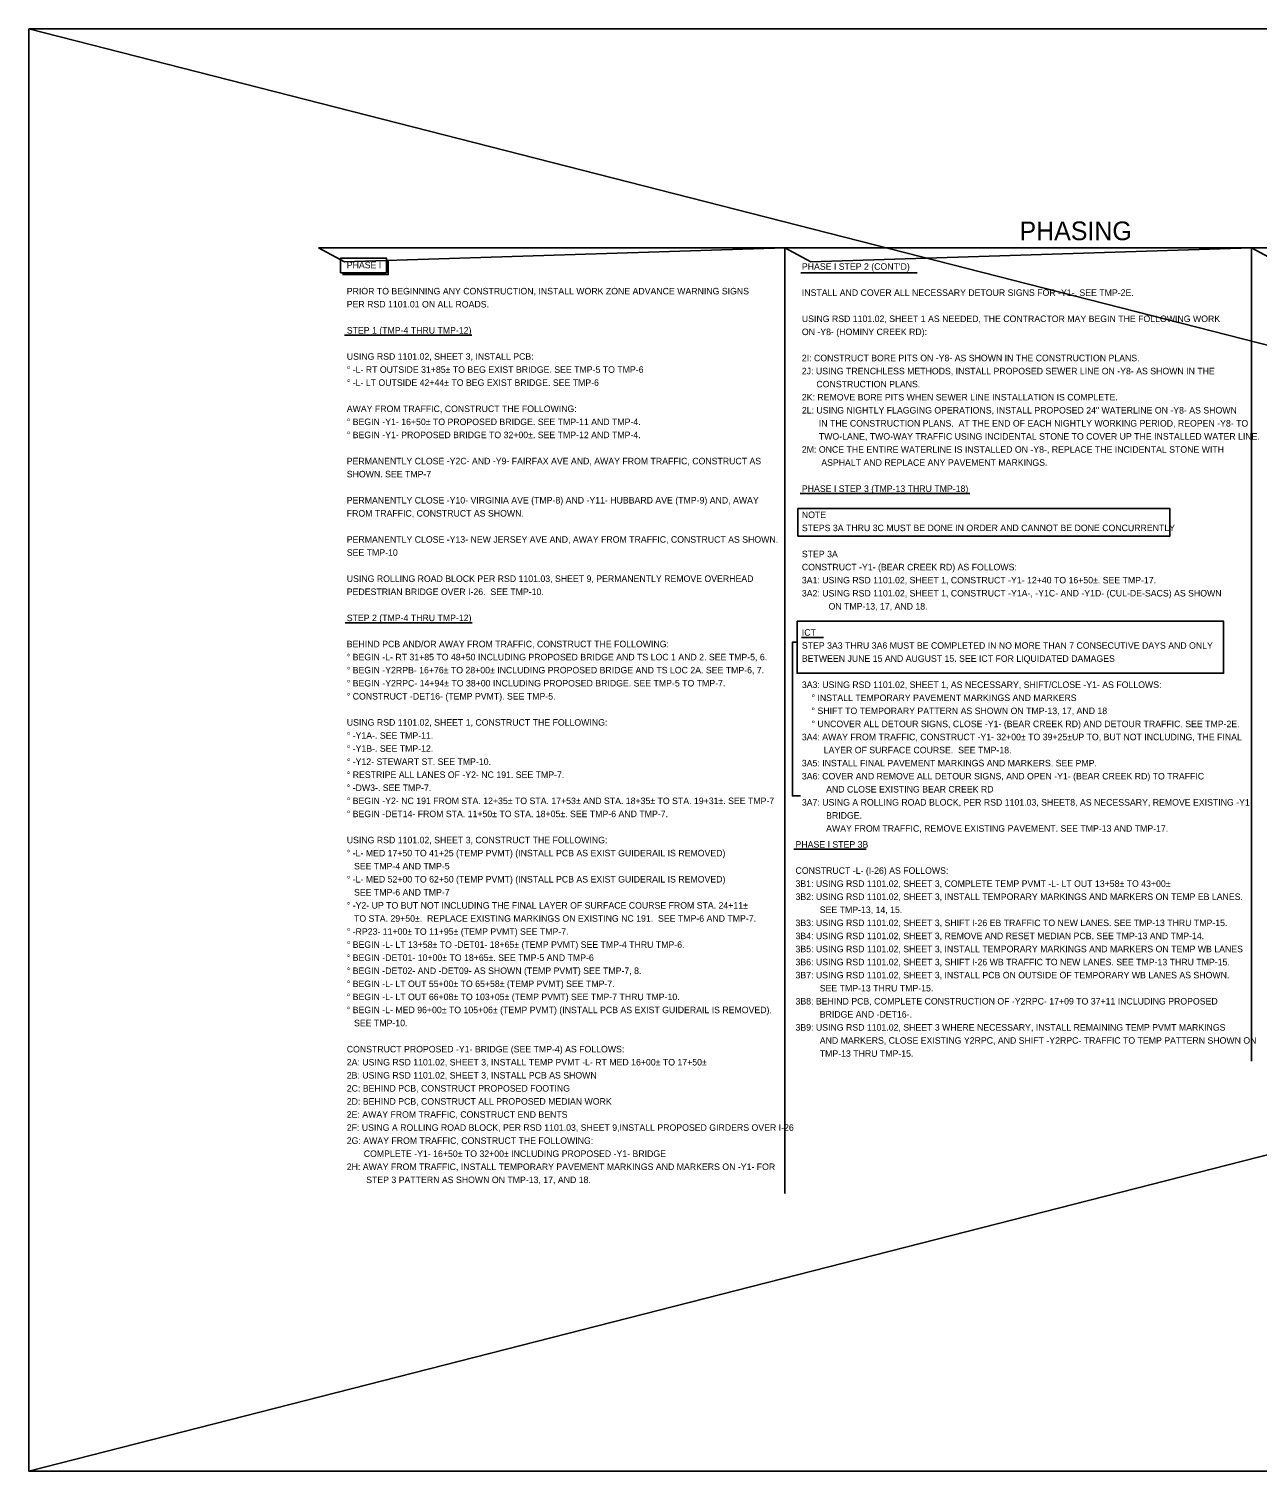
# Model space of a CAD drawing. Extents: x 2483905 to 2494512, y 366160 to 372330.
# Drawn here: x 2486701 to 2488018, y 368441 to 369986 of the extents above; entities that cross this region are included whole.
import ezdxf

# ---------------------------------------------------------------- set-up
doc = ezdxf.new("R2010")
doc.units = 0
for name, color, linetype in [('Scratch_Level_4', 7, 'Continuous'), ('Scratch_Level_6', 7, 'Continuous'), ('TC SHEET BORDER LINE THIN', 7, 'Continuous'), ('TC SHEET TEXT', 7, 'Continuous')]:
    doc.layers.add(name, color=color, linetype=linetype)

msp = doc.modelspace()

# ---------------------------------------------------------------- linework, layer by layer
at = {"layer": 'Scratch_Level_4'}
for p, q in [((2486701.2, 368441.1), (2492754.6, 369986.2)), ((2486701.2, 369986.2), (2492754.6, 368441.1))]:
    msp.add_line(p, q, dxfattribs=at)
msp.add_lwpolyline([(2486701.2, 369986.2), (2492754.6, 369986.2), (2492754.6, 368441.1), (2486701.2, 368441.1)], close=True, dxfattribs=at)
at = {"layer": 'Scratch_Level_6'}
msp.add_lwpolyline([(2487011.6, 369751.7), (2487039.5, 369736.7), (2487511.6, 369751.7), (2487539.5, 369736.7), (2488011.6, 369751.7), (2488039.5, 369736.7)], dxfattribs=at)
at = {"layer": 'TC SHEET BORDER LINE THIN'}
for p, q in [((2488511.6, 369751.7), (2487011.6, 369751.7)), ((2487511.6, 369751.7), (2487511.6, 368738.5)), ((2488011.6, 369751.6), (2488011.6, 368880.2)), ((2487528.7, 369725), (2487646.8, 369725)), ((2487535.4, 369725), (2487653.5, 369725)), ((2487039.7, 369658.1), (2487039.7, 369658.1)), ((2487039.7, 369658.1), (2487176, 369658.1)), ((2487528.1, 369488.5), (2487528.1, 369488.5)), ((2487528.1, 369488.5), (2487710, 369488.5)), ((2487040.3, 369350), (2487040.3, 369350)), ((2487040.3, 369350), (2487176.3, 369350)), ((2487529.5, 369334.2), (2487553.1, 369334.2)), ((2487521.3, 369107.4), (2487598.9, 369107.4))]:
    msp.add_line(p, q, dxfattribs=at)
for points in [[(2487035.4, 369740.6), (2487084.4, 369740.6), (2487084.4, 369725), (2487035.4, 369725)], [(2487525.6, 369472.2), (2487924.3, 369472.2), (2487924.3, 369442.8), (2487525.6, 369442.8)], [(2487524.7, 369351.5), (2487981.9, 369351.5), (2487981.9, 369295.9), (2487524.7, 369295.9)]]:
    msp.add_lwpolyline(points, close=True, dxfattribs=at)
for points in [[(2487086.4, 369738.6), (2487086.4, 369723), (2487037.4, 369723)], [(2487524.7, 369329.1), (2487519.7, 369329.1), (2487519.7, 369164.5), (2487528.2, 369164.5)]]:
    msp.add_lwpolyline(points, dxfattribs=at)

# ---------------------------------------------------------------- texts
for s, p in [('PHASE I', (2487042, 369729.7)), ("PHASE I STEP 2 (CONT'D)", (2487529.8, 369728.1)), ('PRIOR TO BEGINNING ANY CONSTRUCTION, INSTALL WORK ZONE ADVANCE WARNING SIGNS', (2487042, 369701.7)), ('INSTALL AND COVER ALL NECESSARY DETOUR SIGNS FOR -Y1-. SEE TMP-2E.', (2487529.8, 369700.1)), ('PER RSD 1101.01 ON ALL ROADS.', (2487042, 369687.7)), ('USING RSD 1101.02, SHEET 1 AS NEEDED, THE CONTRACTOR MAY BEGIN THE FOLLOWING WORK', (2487529.8, 369672.1)), ('STEP 1 (TMP-4 THRU TMP-12)', (2487042, 369659.7)), ('ON -Y8- (HOMINY CREEK RD):', (2487529.8, 369658.1)), ('USING RSD 1101.02, SHEET 3, INSTALL PCB:', (2487042, 369631.7)), ('2I: CONSTRUCT BORE PITS ON -Y8- AS SHOWN IN THE CONSTRUCTION PLANS.', (2487529.8, 369630.1)), ('° -L- RT OUTSIDE 31+85± TO BEG EXIST BRIDGE. SEE TMP-5 TO TMP-6', (2487042, 369617.7)), ('2J: USING TRENCHLESS METHODS, INSTALL PROPOSED SEWER LINE ON -Y8- AS SHOWN IN THE', (2487529.8, 369616.1)), ('° -L- LT OUTSIDE 42+44± TO BEG EXIST BRIDGE. SEE TMP-6', (2487042, 369603.7)), ('      CONSTRUCTION PLANS.', (2487529.8, 369602.1)), ('AWAY FROM TRAFFIC, CONSTRUCT THE FOLLOWING:', (2487042, 369575.7)), ('2K: REMOVE BORE PITS WHEN SEWER LINE INSTALLATION IS COMPLETE.', (2487529.8, 369588.1)), ('2L: USING NIGHTLY FLAGGING OPERATIONS, INSTALL PROPOSED 24" WATERLINE ON -Y8- AS SHOWN', (2487529.8, 369574.1)), ('° BEGIN -Y1- 16+50± TO PROPOSED BRIDGE. SEE TMP-11 AND TMP-4.', (2487042, 369561.7)), ('       IN THE CONSTRUCTION PLANS.  AT THE END OF EACH NIGHTLY WORKING PERIOD, REOPEN -Y8- TO', (2487529.8, 369560.1)), ('° BEGIN -Y1- PROPOSED BRIDGE TO 32+00±. SEE TMP-12 AND TMP-4.', (2487042, 369547.7)), ('       TWO-LANE, TWO-WAY TRAFFIC USING INCIDENTAL STONE TO COVER UP THE INSTALLED WATER LINE.', (2487529.8, 369546.1)), ('2M: ONCE THE ENTIRE WATERLINE IS INSTALLED ON -Y8-, REPLACE THE INCIDENTAL STONE WITH', (2487529.8, 369532.1)), ('PERMANENTLY CLOSE -Y2C- AND -Y9- FAIRFAX AVE AND, AWAY FROM TRAFFIC, CONSTRUCT AS', (2487042, 369519.7)), ('        ASPHALT AND REPLACE ANY PAVEMENT MARKINGS.', (2487529.8, 369518.1)), ('SHOWN. SEE TMP-7', (2487042, 369505.7)), ('PHASE I STEP 3 (TMP-13 THRU TMP-18)', (2487529.8, 369490.1)), ('PERMANENTLY CLOSE -Y10- VIRGINIA AVE (TMP-8) AND -Y11- HUBBARD AVE (TMP-9) AND, AWAY', (2487042, 369477.7)), ('FROM TRAFFIC, CONSTRUCT AS SHOWN.', (2487042, 369463.7)), ('NOTE', (2487529.8, 369462.1)), ('PERMANENTLY CLOSE -Y13- NEW JERSEY AVE AND, AWAY FROM TRAFFIC, CONSTRUCT AS SHOWN.', (2487042, 369435.7)), ('STEPS 3A THRU 3C MUST BE DONE IN ORDER AND CANNOT BE DONE CONCURRENTLY', (2487529.8, 369448.1)), ('SEE TMP-10', (2487042, 369421.7)), ('STEP 3A', (2487529.8, 369420.1)), ('CONSTRUCT -Y1- (BEAR CREEK RD) AS FOLLOWS:', (2487529.8, 369406.1)), ('USING ROLLING ROAD BLOCK PER RSD 1101.03, SHEET 9, PERMANENTLY REMOVE OVERHEAD ', (2487042, 369393.7)), ('3A1: USING RSD 1101.02, SHEET 1, CONSTRUCT -Y1- 12+40 TO 16+50±. SEE TMP-17.', (2487529.8, 369392.1)), ('PEDESTRIAN BRIDGE OVER I-26.  SEE TMP-10.', (2487042, 369379.7)), ('3A2: USING RSD 1101.02, SHEET 1, CONSTRUCT -Y1A-, -Y1C- AND -Y1D- (CUL-DE-SACS) AS SHOWN', (2487529.8, 369378.1)), ('           ON TMP-13, 17, AND 18.', (2487529.8, 369364.1)), ('STEP 2 (TMP-4 THRU TMP-12)', (2487042, 369351.7)), ('ICT', (2487529.8, 369336.1)), ('BEHIND PCB AND/OR AWAY FROM TRAFFIC, CONSTRUCT THE FOLLOWING:', (2487042, 369323.7)), ('STEP 3A3 THRU 3A6 MUST BE COMPLETED IN NO MORE THAN 7 CONSECUTIVE DAYS AND ONLY', (2487529.8, 369322.1)), ('° BEGIN -L- RT 31+85 TO 48+50 INCLUDING PROPOSED BRIDGE AND TS LOC 1 AND 2. SEE TMP-5, 6.', (2487042, 369309.7)), ('BETWEEN JUNE 15 AND AUGUST 15. SEE ICT FOR LIQUIDATED DAMAGES', (2487529.8, 369308.1)), ('° BEGIN -Y2RPB- 16+76± TO 28+00± INCLUDING PROPOSED BRIDGE AND TS LOC 2A. SEE TMP-6, 7.', (2487042, 369295.7)), ('° BEGIN -Y2RPC- 14+94± TO 38+00 INCLUDING PROPOSED BRIDGE. SEE TMP-5 TO TMP-7.', (2487042, 369281.7)), ('3A3: USING RSD 1101.02, SHEET 1, AS NECESSARY, SHIFT/CLOSE -Y1- AS FOLLOWS:', (2487529.8, 369280.1)), ('° CONSTRUCT -DET16- (TEMP PVMT). SEE TMP-5.', (2487042, 369267.7)), ('    ° INSTALL TEMPORARY PAVEMENT MARKINGS AND MARKERS', (2487529.8, 369266.1)), ('    ° SHIFT TO TEMPORARY PATTERN AS SHOWN ON TMP-13, 17, AND 18', (2487529.8, 369252.1)), ('USING RSD 1101.02, SHEET 1, CONSTRUCT THE FOLLOWING:', (2487042, 369239.7)), ('    ° UNCOVER ALL DETOUR SIGNS, CLOSE -Y1- (BEAR CREEK RD) AND DETOUR TRAFFIC. SEE TMP-2E.', (2487529.8, 369238.1)), ('° -Y1A-. SEE TMP-11.', (2487042, 369225.7)), ('3A4: AWAY FROM TRAFFIC, CONSTRUCT -Y1- 32+00± TO 39+25±UP TO, BUT NOT INCLUDING, THE FINAL', (2487529.8, 369224.1)), ('° -Y1B-. SEE TMP-12.', (2487042, 369211.7)), ('         LAYER OF SURFACE COURSE.  SEE TMP-18.', (2487529.8, 369210.1)), ('° -Y12- STEWART ST. SEE TMP-10.', (2487042, 369197.7)), ('3A5: INSTALL FINAL PAVEMENT MARKINGS AND MARKERS. SEE PMP.', (2487529.8, 369196.1)), ('° RESTRIPE ALL LANES OF -Y2- NC 191. SEE TMP-7.', (2487042, 369183.7)), ('3A6: COVER AND REMOVE ALL DETOUR SIGNS, AND OPEN -Y1- (BEAR CREEK RD) TO TRAFFIC', (2487529.8, 369182.1)), ('° -DW3-. SEE TMP-7.', (2487042, 369169.7)), ('          AND CLOSE EXISTING BEAR CREEK RD', (2487529.8, 369168.1)), ('° BEGIN -Y2- NC 191 FROM STA. 12+35± TO STA. 17+53± AND STA. 18+35± TO STA. 19+31±. SEE TMP-7', (2487042, 369155.7)), ('° BEGIN -DET14- FROM STA. 11+50± TO STA. 18+05±. SEE TMP-6 AND TMP-7.', (2487042, 369141.7)), ('3A7: USING A ROLLING ROAD BLOCK, PER RSD 1101.03, SHEET8, AS NECESSARY, REMOVE EXISTING -Y1- ', (2487529.8, 369154.1)), ('          AWAY FROM TRAFFIC, REMOVE EXISTING PAVEMENT. SEE TMP-13 AND TMP-17.', (2487529.8, 369126.1)), ('          BRIDGE.', (2487529.8, 369140.1)), ('USING RSD 1101.02, SHEET 3, CONSTRUCT THE FOLLOWING:', (2487042, 369113.7)), ('° -L- MED 17+50 TO 41+25 (TEMP PVMT) (INSTALL PCB AS EXIST GUIDERAIL IS REMOVED)', (2487042, 369099.7)), ('PHASE I STEP 3B', (2487523, 369109)), ('   SEE TMP-4 AND TMP-5', (2487042, 369085.7)), ('CONSTRUCT -L- (I-26) AS FOLLOWS:', (2487523, 369081)), ('° -L- MED 52+00 TO 62+50 (TEMP PVMT) (INSTALL PCB AS EXIST GUIDERAIL IS REMOVED)', (2487042, 369071.7)), ('3B1: USING RSD 1101.02, SHEET 3, COMPLETE TEMP PVMT -L- LT OUT 13+58± TO 43+00±', (2487523, 369067)), ('   SEE TMP-6 AND TMP-7', (2487042, 369057.7)), ('3B2: USING RSD 1101.02, SHEET 3, INSTALL TEMPORARY MARKINGS AND MARKERS ON TEMP EB LANES.', (2487523, 369053)), ('° -Y2- UP TO BUT NOT INCLUDING THE FINAL LAYER OF SURFACE COURSE FROM STA. 24+11±', (2487042, 369043.7)), ('          SEE TMP-13, 14, 15.', (2487523, 369039)), ('   TO STA. 29+50±.  REPLACE EXISTING MARKINGS ON EXISTING NC 191.  SEE TMP-6 AND TMP-7.', (2487042, 369029.7)), ('3B3: USING RSD 1101.02, SHEET 3, SHIFT I-26 EB TRAFFIC TO NEW LANES. SEE TMP-13 THRU TMP-15.', (2487523, 369025)), ('° -RP23- 11+00± TO 11+95± (TEMP PVMT) SEE TMP-7.', (2487042, 369015.7)), ('3B4: USING RSD 1101.02, SHEET 3, REMOVE AND RESET MEDIAN PCB. SEE TMP-13 AND TMP-14.', (2487523, 369011)), ('° BEGIN -L- LT 13+58± TO -DET01- 18+65± (TEMP PVMT) SEE TMP-4 THRU TMP-6.', (2487042, 369001.7)), ('° BEGIN -DET01- 10+00± TO 18+65±. SEE TMP-5 AND TMP-6', (2487042, 368987.7)), ('3B5: USING RSD 1101.02, SHEET 3, INSTALL TEMPORARY MARKINGS AND MARKERS ON TEMP WB LANES', (2487523, 368997)), ('° BEGIN -DET02- AND -DET09- AS SHOWN (TEMP PVMT) SEE TMP-7, 8.', (2487042, 368973.7)), ('3B6: USING RSD 1101.02, SHEET 3, SHIFT I-26 WB TRAFFIC TO NEW LANES. SEE TMP-13 THRU TMP-15.', (2487523, 368983)), ('° BEGIN -L- LT OUT 55+00± TO 65+58± (TEMP PVMT) SEE TMP-7.', (2487042, 368959.7)), ('3B7: USING RSD 1101.02, SHEET 3, INSTALL PCB ON OUTSIDE OF TEMPORARY WB LANES AS SHOWN. ', (2487523, 368969)), ('° BEGIN -L- LT OUT 66+08± TO 103+05± (TEMP PVMT) SEE TMP-7 THRU TMP-10.', (2487042, 368945.7)), ('3B8: BEHIND PCB, COMPLETE CONSTRUCTION OF -Y2RPC- 17+09 TO 37+11 INCLUDING PROPOSED', (2487523, 368941)), ('          SEE TMP-13 THRU TMP-15.', (2487523, 368955)), ('° BEGIN -L- MED 96+00± TO 105+06± (TEMP PVMT) (INSTALL PCB AS EXIST GUIDERAIL IS REMOVED).', (2487042, 368931.7)), ('          BRIDGE AND -DET16-.', (2487523, 368927)), ('   SEE TMP-10.', (2487042, 368917.7)), ('3B9: USING RSD 1101.02, SHEET 3 WHERE NECESSARY, INSTALL REMAINING TEMP PVMT MARKINGS', (2487523, 368913)), ('          AND MARKERS, CLOSE EXISTING Y2RPC, AND SHIFT -Y2RPC- TRAFFIC TO TEMP PATTERN SHOWN ON', (2487523, 368899)), ('CONSTRUCT PROPOSED -Y1- BRIDGE (SEE TMP-4) AS FOLLOWS:', (2487042, 368889.7)), ('          TMP-13 THRU TMP-15.', (2487523, 368885)), ('2A: USING RSD 1101.02, SHEET 3, INSTALL TEMP PVMT -L- RT MED 16+00± TO 17+50±', (2487042, 368875.7)), ('2B: USING RSD 1101.02, SHEET 3, INSTALL PCB AS SHOWN', (2487042, 368861.7)), ('2C: BEHIND PCB, CONSTRUCT PROPOSED FOOTING', (2487042, 368847.7)), ('2D: BEHIND PCB, CONSTRUCT ALL PROPOSED MEDIAN WORK', (2487042, 368833.7)), ('2E: AWAY FROM TRAFFIC, CONSTRUCT END BENTS ', (2487042, 368819.7)), ('2F: USING A ROLLING ROAD BLOCK, PER RSD 1101.03, SHEET 9,INSTALL PROPOSED GIRDERS OVER I-26', (2487042, 368805.7)), ('2G: AWAY FROM TRAFFIC, CONSTRUCT THE FOLLOWING:', (2487042, 368791.7)), ('       COMPLETE -Y1- 16+50± TO 32+00± INCLUDING PROPOSED -Y1- BRIDGE', (2487042, 368777.7)), ('2H: AWAY FROM TRAFFIC, INSTALL TEMPORARY PAVEMENT MARKINGS AND MARKERS ON -Y1- FOR ', (2487042, 368763.7)), ('        STEP 3 PATTERN AS SHOWN ON TMP-13, 17, AND 18.', (2487042, 368749.7))]:
    msp.add_text(s, height=7, dxfattribs=at).set_placement(p)
at = {"layer": 'TC SHEET TEXT'}
msp.add_text('PHASING', height=20, rotation=359.9999, dxfattribs=at).set_placement((2487763.1, 369759.8))

doc.saveas('drawing.dxf')
